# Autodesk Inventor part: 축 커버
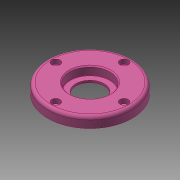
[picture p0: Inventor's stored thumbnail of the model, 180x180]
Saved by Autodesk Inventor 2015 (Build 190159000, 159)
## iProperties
Created: 2015-10
Part Number: 축 커버
Document SubType Name: Modeling
Designer: mdu
Density: 1 g/cm^3
Material: 강철, 연강
Appearance: 분홍색
Author: mdu
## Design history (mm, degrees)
sketch "스케치1"
  geometry: C1 r 40 at (0, 0) reference; C2 r 26 at (0, 0) reference; 1 further point
  node "참조1"
  node "참조2"
extrude "돌출1" new body sketch "스케치1" distance "d0" = 10; taper "d1" = 0 deg
extrude "돌출2" join sketch "스케치1" distance "d2" = 3; taper "d3" = 0 deg
hole "구멍1" diameter "d6" = 27; stored, may be unused: countersink angle "d10" = 90 deg, drill point angle "d12" = 118 deg; dims "d4" = 10, "d5" = 10, "d7" = 6, "d8" = 38, "d9" = 8, "d11" = 8
sketch "스케치2"
  geometry: C1 r 20 at (0, 0); 1 further point
  constraints: 1 centre point, 1 coincident
  dimensions: "d13" = 40 diameter of C1
extrude "돌출3" cut sketch "스케치2" distance "d14" = 3; taper "d15" = 0 deg
sketch "스케치3"
  geometry: C1 r 1.621 at (0, 32.5) reference; 1 further point
hole "구멍2" sketch "스케치3" at (0, 32.5) diameter "d16" = 4.5; stored, may be unused: countersink angle "d20" = 90 deg, drill point angle "d22" = 118 deg; dims "d17" = 6, "d18" = 8, "d19" = 4.4, "d21" = 8
fillet "모깎기1" dims "d26" = 3, "d27" = 0.3
chamfer "모따기1" distance "d28" = 1; stored, may be unused: second distance "d29" = 2, angle "d30" = 45 deg
node "솔리드1"
pattern_circular "원형 패턴1" dims angle "d24" = 360 deg
node "참조3"
